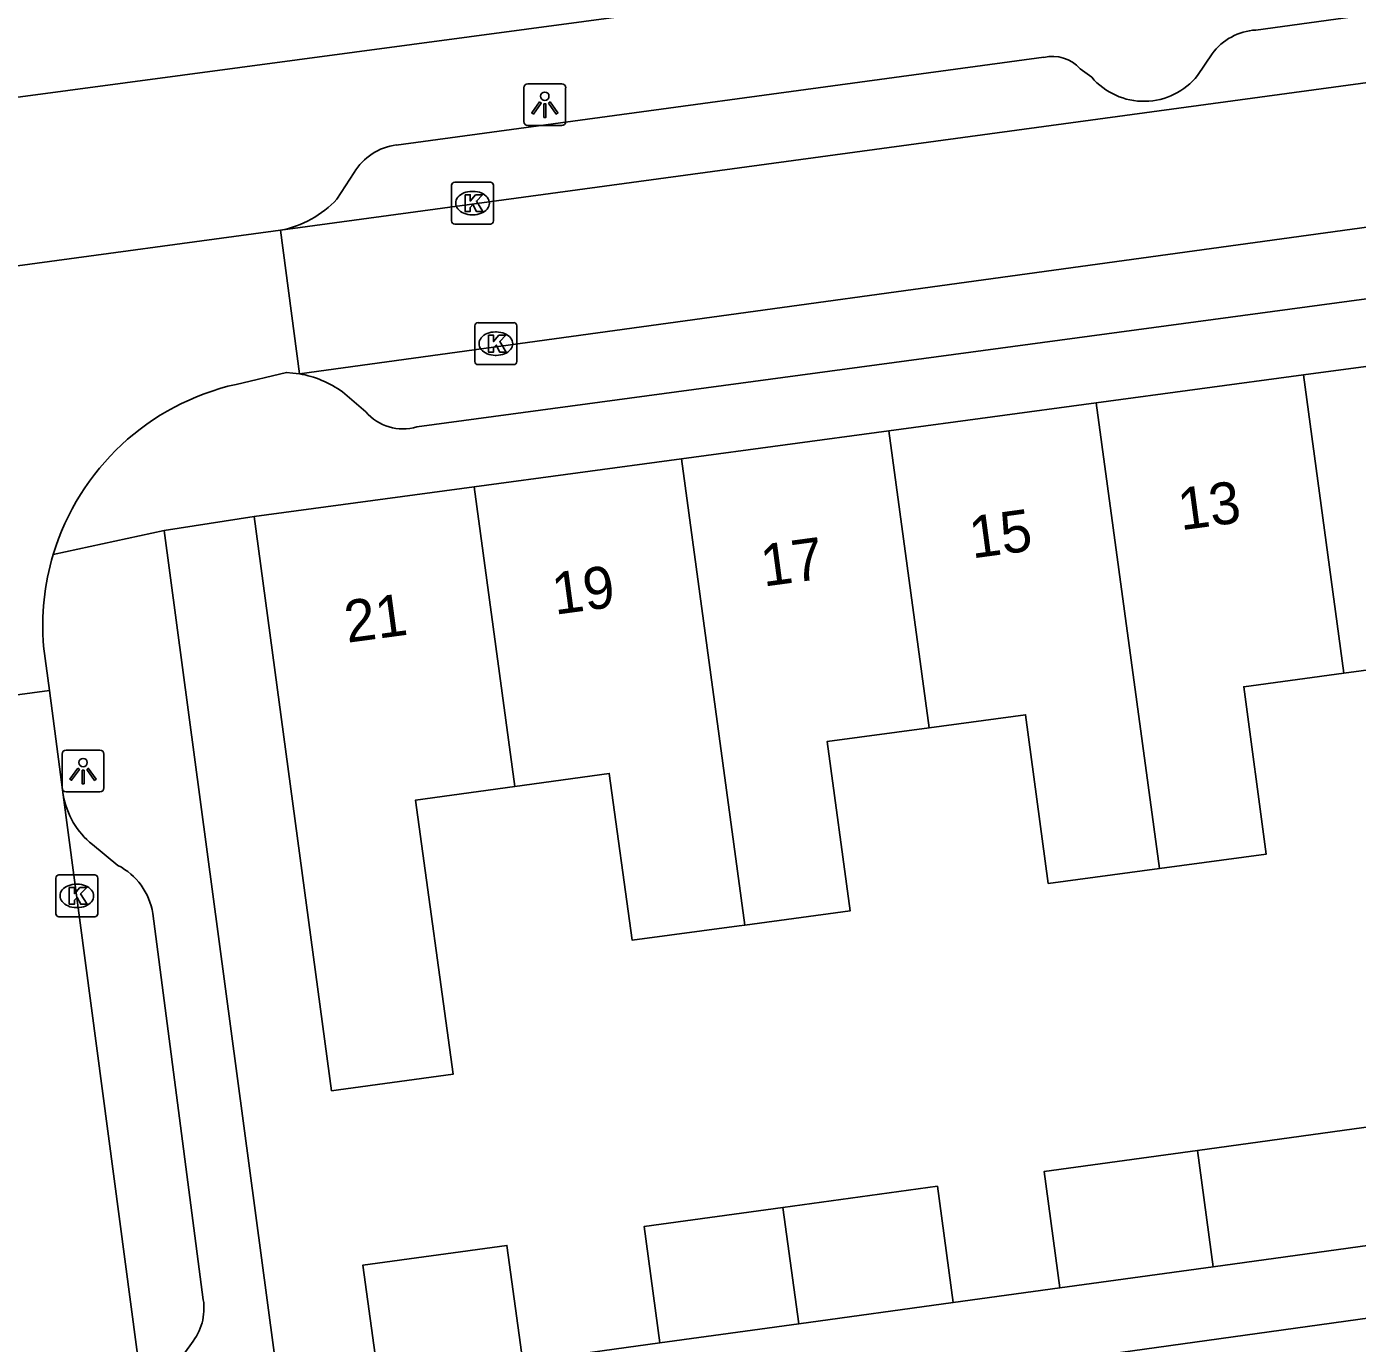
# Model space of a CAD drawing. Extents: x 163150 to 163546, y 380933 to 381635.
# Drawn here: x 163324.23 to 163355.98, y 381463.34 to 381494.73 of the extents above; entities that cross this region are included whole.
import ezdxf

# ---------------------------------------------------------------- set-up
doc = ezdxf.new("R2010")
doc.units = 0
for name, color, linetype in [('IMGEO_Kolk', 7, 'Continuous'), ('IMGEO_Lichtpunt', 7, 'Continuous'), ('IMGEO_Pand', 7, 'Continuous'), ('IMGEO_Pand_nummerreeks', 7, 'Continuous'), ('IMGEO_Rijbaan_lokaal_open', 7, 'Continuous'), ('IMGEO_Voetpad_open', 7, 'Continuous')]:
    doc.layers.add(name, color=color, linetype=linetype)

msp = doc.modelspace()

# ---------------------------------------------------------------- linework, layer by layer
at = {"layer": 'IMGEO_Kolk'}
for p, q in [((163334.367, 381490.098), (163334.367, 381490.95)), ((163334.442, 381491.024), (163335.294, 381491.024)), ((163335.368, 381490.95), (163335.368, 381490.098)), ((163334.855, 381490.804), (163334.88, 381490.804)), ((163335.294, 381490.024), (163334.442, 381490.024)), ((163334.878, 381490.244), (163334.853, 381490.244)), ((163334.924, 381486.747), (163334.924, 381487.599)), ((163334.999, 381487.673), (163335.851, 381487.673)), ((163335.412, 381487.453), (163335.437, 381487.453)), ((163335.925, 381487.599), (163335.925, 381486.747)), ((163335.435, 381486.893), (163335.41, 381486.893)), ((163335.851, 381486.673), (163334.999, 381486.673)), ((163324.927, 381473.58), (163324.927, 381474.432)), ((163325.002, 381474.506), (163325.854, 381474.506)), ((163325.928, 381474.432), (163325.928, 381473.58)), ((163325.415, 381474.286), (163325.44, 381474.286)), ((163325.854, 381473.506), (163325.002, 381473.506)), ((163325.438, 381473.726), (163325.413, 381473.726))]:
    msp.add_line(p, q, dxfattribs=at)
for points in [[(163334.367, 381490.098), (163334.367, 381490.95)], [(163334.442, 381491.024), (163335.294, 381491.024)], [(163335.368, 381490.95), (163335.368, 381490.098)], [(163334.688, 381490.724), (163334.811, 381490.724), (163334.811, 381490.573), (163334.941, 381490.724), (163335.105, 381490.724), (163334.959, 381490.573), (163335.112, 381490.324), (163334.96, 381490.324), (163334.875, 381490.488), (163334.811, 381490.421), (163334.811, 381490.324), (163334.688, 381490.324), (163334.688, 381490.724)], [(163335.294, 381490.024), (163334.442, 381490.024)], [(163334.924, 381486.747), (163334.924, 381487.599)], [(163334.999, 381487.673), (163335.851, 381487.673)], [(163335.925, 381487.599), (163335.925, 381486.747)], [(163335.245, 381487.373), (163335.368, 381487.373), (163335.368, 381487.222), (163335.498, 381487.373), (163335.662, 381487.373), (163335.516, 381487.222), (163335.669, 381486.973), (163335.517, 381486.973), (163335.432, 381487.137), (163335.368, 381487.07), (163335.368, 381486.973), (163335.245, 381486.973), (163335.245, 381487.373)], [(163335.851, 381486.673), (163334.999, 381486.673)], [(163324.927, 381473.58), (163324.927, 381474.432)], [(163325.002, 381474.506), (163325.854, 381474.506)], [(163325.928, 381474.432), (163325.928, 381473.58)], [(163325.248, 381474.206), (163325.371, 381474.206), (163325.371, 381474.055), (163325.501, 381474.206), (163325.665, 381474.206), (163325.519, 381474.055), (163325.672, 381473.806), (163325.52, 381473.806), (163325.435, 381473.97), (163325.371, 381473.903), (163325.371, 381473.806), (163325.248, 381473.806), (163325.248, 381474.206)], [(163325.854, 381473.506), (163325.002, 381473.506)]]:
    msp.add_lwpolyline(points, dxfattribs=at)
for centre, start, end in [((163334.444, 381490.948), 91.552, 178.448), ((163334.444, 381490.948), 91.552, 178.448), ((163335.292, 381490.948), 1.552, 88.448), ((163335.292, 381490.948), 1.552, 88.448), ((163334.444, 381490.1), 181.552, 268.448), ((163334.444, 381490.1), 181.552, 268.448), ((163335.292, 381490.1), 271.552, 358.448), ((163335.292, 381490.1), 271.552, 358.448), ((163335.001, 381487.597), 91.552, 178.448), ((163335.001, 381487.597), 91.552, 178.448), ((163335.849, 381487.597), 1.552, 88.448), ((163335.849, 381487.597), 1.552, 88.448), ((163335.001, 381486.749), 181.552, 268.448), ((163335.001, 381486.749), 181.552, 268.448), ((163335.849, 381486.749), 271.552, 358.448), ((163335.849, 381486.749), 271.552, 358.448), ((163325.004, 381474.43), 91.552, 178.448), ((163325.004, 381474.43), 91.552, 178.448), ((163325.852, 381474.43), 1.552, 88.448), ((163325.852, 381474.43), 1.552, 88.448), ((163325.004, 381473.582), 181.552, 268.448), ((163325.004, 381473.582), 181.552, 268.448), ((163325.852, 381473.582), 271.552, 358.448), ((163325.852, 381473.582), 271.552, 358.448)]:
    msp.add_arc(centre, 0.0765, start, end, dxfattribs=at)
for centre, major_axis, ratio, start_param, end_param in [((163334.854, 381490.524), (-0.387, 0.002), 0.722429, 4.712389, 7.853982), ((163334.879, 381490.524), (-0.39, 0.002), 0.717154, 1.570796, 4.712389), ((163335.411, 381487.173), (-0.387, 0.002), 0.722429, 4.712389, 7.853982), ((163335.436, 381487.173), (-0.39, 0.002), 0.717154, 1.570796, 4.712389), ((163325.414, 381474.006), (-0.387, 0.002), 0.722429, 4.712389, 7.853982), ((163325.439, 381474.006), (-0.39, 0.002), 0.717154, 1.570796, 4.712389)]:
    msp.add_ellipse(centre, major_axis=major_axis, ratio=ratio, start_param=start_param, end_param=end_param, dxfattribs=at)
at = {"layer": 'IMGEO_Lichtpunt'}
for p, q in [((163336.093, 381493.274), (163336.093, 381492.467)), ((163336.093, 381493.274), (163336.093, 381492.467)), ((163336.995, 381493.369), (163336.187, 381493.369)), ((163336.995, 381493.369), (163336.187, 381493.369)), ((163337.089, 381492.467), (163337.089, 381493.274)), ((163337.089, 381492.467), (163337.089, 381493.274)), ((163336.187, 381492.373), (163336.995, 381492.373)), ((163336.187, 381492.373), (163336.995, 381492.373)), ((163325.078, 381477.387), (163325.078, 381476.58)), ((163325.078, 381477.387), (163325.078, 381476.58)), ((163325.98, 381477.482), (163325.172, 381477.482)), ((163325.98, 381477.482), (163325.172, 381477.482)), ((163326.074, 381476.58), (163326.074, 381477.387)), ((163326.074, 381476.58), (163326.074, 381477.387)), ((163325.172, 381476.486), (163325.98, 381476.486)), ((163325.172, 381476.486), (163325.98, 381476.486))]:
    msp.add_line(p, q, dxfattribs=at)
for points in [[(163336.467, 381492.938), (163336.506, 381492.91), (163336.318, 381492.648), (163336.28, 381492.675), (163336.467, 381492.938)], [(163336.569, 381492.89), (163336.616, 381492.89), (163336.616, 381492.568), (163336.569, 381492.568), (163336.569, 381492.89)], [(163336.679, 381492.91), (163336.717, 381492.937), (163336.904, 381492.675), (163336.865, 381492.647), (163336.679, 381492.91)], [(163325.452, 381477.051), (163325.491, 381477.023), (163325.303, 381476.761), (163325.265, 381476.788), (163325.452, 381477.051)], [(163325.554, 381477.003), (163325.601, 381477.003), (163325.601, 381476.681), (163325.554, 381476.681), (163325.554, 381477.003)], [(163325.664, 381477.023), (163325.702, 381477.05), (163325.889, 381476.788), (163325.85, 381476.76), (163325.664, 381477.023)]]:
    msp.add_lwpolyline(points, dxfattribs=at)
for centre in [(163336.592, 381493.072), (163325.577, 381477.185)]:
    msp.add_circle(centre, 0.0994, dxfattribs=at)
for centre, start, end in [((163336.187, 381493.274), 90, 180), ((163336.187, 381493.274), 90, 180), ((163336.995, 381493.274), 0, 90), ((163336.995, 381493.274), 0, 90), ((163336.187, 381492.467), 180, 270), ((163336.187, 381492.467), 180, 270), ((163336.995, 381492.467), 270, 0), ((163336.995, 381492.467), 270, 360), ((163325.172, 381477.387), 90, 180), ((163325.172, 381477.387), 90, 180), ((163325.98, 381477.387), 0, 90), ((163325.98, 381477.387), 0, 90), ((163325.172, 381476.58), 180, 270), ((163325.172, 381476.58), 180, 270), ((163325.98, 381476.58), 270, 0), ((163325.98, 381476.58), 270, 360)]:
    msp.add_arc(centre, 0.0946, start, end, dxfattribs=at)
at = {"layer": 'IMGEO_Pand'}
for points in [[(163354.692, 381486.426), (163359.639, 381487.093)], [(163349.747, 381485.759), (163354.692, 381486.426)], [(163354.692, 381486.426), (163355.655, 381479.315)], [(163344.801, 381485.092), (163349.747, 381485.759)], [(163351.251, 381474.659), (163349.747, 381485.759)], [(163339.855, 381484.424), (163344.801, 381485.092)], [(163344.801, 381485.092), (163345.76, 381478.015)], [(163334.91, 381483.757), (163339.855, 381484.424)], [(163341.361, 381473.309), (163339.855, 381484.424)], [(163329.66, 381483.049), (163334.91, 381483.757)], [(163334.91, 381483.757), (163335.877, 381476.616)], [(163335.877, 381476.616), (163333.51, 381476.291), (163334.409, 381469.758), (163331.674, 381469.38), (163331.507, 381469.359), (163329.66, 381483.049)], [(163361.145, 381475.976), (163358.436, 381475.61), (163357.895, 381479.617), (163355.655, 381479.315)], [(163355.655, 381479.315), (163353.264, 381478.992), (163353.802, 381475.003), (163351.251, 381474.659)], [(163351.251, 381474.659), (163348.603, 381474.302), (163348.06, 381478.325), (163345.76, 381478.015)], [(163345.76, 381478.015), (163343.33, 381477.687), (163343.875, 381473.648), (163341.361, 381473.309)], [(163341.361, 381473.309), (163341.231, 381473.291), (163338.677, 381472.947), (163338.13, 381476.926), (163335.877, 381476.616)], [(163352.162, 381467.938), (163357.104, 381468.618), (163357.479, 381465.844)], [(163348.878, 381464.66), (163348.502, 381467.434), (163352.162, 381467.938)], [(163352.162, 381467.938), (163352.538, 381465.163)], [(163342.273, 381466.577), (163345.958, 381467.084), (163346.334, 381464.309)], [(163339.339, 381463.347), (163338.958, 381466.12), (163342.273, 381466.577)], [(163342.273, 381466.577), (163342.649, 381463.802)], [(163357.479, 381465.844), (163352.538, 381465.163)], [(163332.631, 381462.423), (163332.25, 381465.197), (163335.686, 381465.67), (163336.067, 381462.896)], [(163352.538, 381465.163), (163348.878, 381464.66)], [(163346.334, 381464.309), (163342.649, 381463.802)], [(163342.649, 381463.802), (163339.339, 381463.347)]]:
    msp.add_lwpolyline(points, dxfattribs=at)
at = {"layer": 'IMGEO_Rijbaan_lokaal_open'}
for points in [[(163330.288, 381489.877), (163382.807, 381497.014)], [(163383.048, 381493.637), (163330.736, 381486.454)], [(163317.382, 381488.131), (163330.288, 381489.877)], [(163330.736, 381486.454), (163330.288, 381489.877)], [(163330.736, 381486.454), (163330.578, 381486.471), (163330.427, 381486.487), (163329.226, 381486.202)], [(163324.634, 381479.959), (163324.774, 381478.904)], [(163321.405, 381478.446), (163324.774, 381478.904)], [(163324.774, 381478.904), (163325.105, 381476.415)], [(163325.105, 381476.415), (163331.157, 381430.873)]]:
    msp.add_lwpolyline(points, dxfattribs=at)
for centre, radius, start, end in [((163330.521, 381480.439), 5.907, 102.6672, 163.2095), ((163330.497, 381480.442), 5.883, 163.1743, 184.7095)]:
    msp.add_arc(centre, radius, start, end, dxfattribs=at)
at = {"layer": 'IMGEO_Voetpad_open'}
for points in [[(163386.878, 381501.46), (163323.846, 381493.024)], [(163353.554, 381494.651), (163379.575, 381498.232)], [(163352.165, 381493.565), (163352.51, 381494.084)], [(163333.048, 381491.909), (163348.498, 381494)], [(163349.36, 381493.729), (163349.638, 381493.525)], [(163331.633, 381490.62), (163332.042, 381491.253)], [(163361.681, 381488.978), (163333.539, 381485.19)], [(163332.322, 381485.551), (163331.765, 381486.023)], [(163329.66, 381483.049), (163327.51, 381482.721)], [(163324.866, 381482.145), (163327.51, 381482.721)], [(163327.51, 381482.721), (163330.269, 381462.107)], [(163325.801, 381475.231), (163326.408, 381474.733)], [(163327.241, 381473.586), (163328.445, 381464.376)], [(163346.334, 381464.309), (163348.878, 381464.66)], [(163339.808, 381461.652), (163358.388, 381464.242), (163358.581, 381462.857)], [(163328.161, 381463.336), (163327.918, 381462.994)], [(163336.067, 381462.896), (163339.339, 381463.347)]]:
    msp.add_lwpolyline(points, dxfattribs=at)
for centre, radius, start, end in [((163353.641, 381493.247), 1.407, 93.5297, 143.4834), ((163348.697, 381493.126), 0.896, 42.2697, 102.8255), ((163350.885, 381494.592), 1.641, 220.5482, 321.2655), ((163333.225, 381490.539), 1.382, 97.3507, 148.865), ((163329.829, 381492.297), 2.463, 280.7449, 317.089), ((163330.315, 381484.005), 2.485, 54.3001, 80.2469), ((163333.201, 381486.282), 1.143, 219.7537, 287.2024), ((163326.978, 381476.719), 1.897, 189.2297, 231.6675), ((163325.706, 381473.347), 1.553, 8.8424, 63.135), ((163327.14, 381464.174), 1.321, 320.6437, 8.8088)]:
    msp.add_arc(centre, radius, start, end, dxfattribs=at)

# ---------------------------------------------------------------- texts
at = {"layer": 'IMGEO_Pand_nummerreeks'}
for s, rotation, p in [('13', 7.6829, (163351.765, 381482.721)), ('15', 7.6829, (163346.788, 381482.05)), ('17', 7.6829, (163341.812, 381481.378)), ('19', 7.6834, (163336.835, 381480.707)), ('21', 7.6829, (163331.88, 381480.039))]:
    msp.add_text(s, height=1, rotation=rotation, dxfattribs=at).set_placement(p)

doc.saveas('drawing.dxf')
